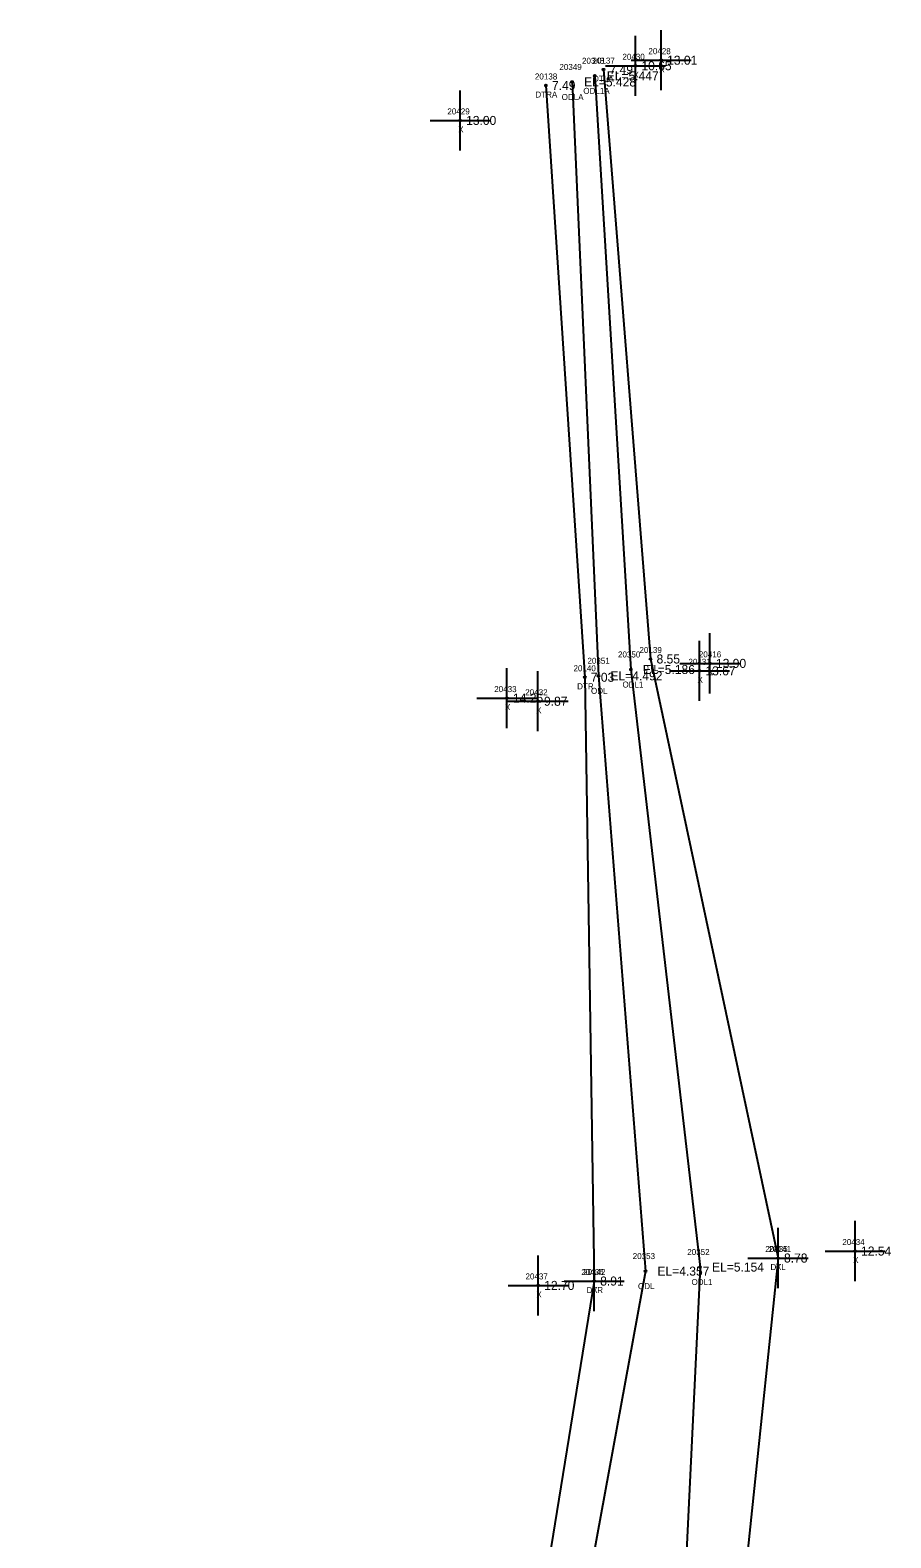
# Model space of a CAD drawing. Extents: x 2072302 to 2072980, y 127650 to 129736.
# Drawn here: x 2072308.2 to 2072451.4, y 128316.1 to 128566.9 of the extents above; entities that cross this region are included whole.
import ezdxf

# ---------------------------------------------------------------- set-up
doc = ezdxf.new("R2010")
doc.units = 0
for name, color, linetype in [('RD_EX_H2O', 7, 'Continuous'), ('RD_EX_H2O_txCode', 7, 'Continuous'), ('RD_EX_Misc', 7, 'Continuous'), ('RD_EX_Misc_txCode', 7, 'Continuous'), ('RD_EX_TX_H2O_ELEV', 7, 'Continuous'), ('RD_EX_TX_Misc_ELEV', 7, 'Continuous'), ('RD_SMD_Locator', 7, 'Continuous')]:
    doc.layers.add(name, color=color, linetype=linetype)

msp = doc.modelspace()

# ---------------------------------------------------------------- linework, layer by layer
at = {"layer": 'RD_EX_H2O'}
for points in [[(2072402.16, 128559.26), (2072408.19, 128460.51), (2072419.68, 128361.12), (2072413.76, 128237.7), (2072402.36, 128177.9), (2072384.5, 128133.27), (2072364.13, 128111.41), (2072366.88, 128103.31), (2072335.48, 128099.87), (2072319.81, 128071.7)], [(2072403.62, 128560.29), (2072411.45, 128462.26), (2072432.66, 128362.62), (2072419.56, 128236.49), (2072406.7, 128177.6), (2072390.06, 128127.17), (2072380.51, 128114.72)], [(2072394.05, 128557.65), (2072400.51, 128459.22), (2072402.07, 128358.79), (2072383.51, 128244.18), (2072363.41, 128182.49), (2072364.78, 128146.69), (2072330.57, 128113.46), (2072324.79, 128105.03), (2072308.22, 128075.71)], [(2072398.39, 128558.24), (2072402.78, 128459.46), (2072410.6, 128360.44), (2072388.96, 128242.4), (2072374.63, 128179.98), (2072371.63, 128143.83), (2072337.87, 128113.26), (2072328.43, 128104.04), (2072312.51, 128073.95)]]:
    msp.add_lwpolyline(points, dxfattribs=at)
at = {"layer": 'RD_EX_Misc'}
for p, q in [((2072413.21, 128556.86), (2072413.21, 128566.86)), ((2072408.93, 128555.93), (2072408.93, 128565.93)), ((2072408.21, 128561.86), (2072418.21, 128561.86)), ((2072403.93, 128560.93), (2072413.93, 128560.93)), ((2072379.76, 128546.84), (2072379.76, 128556.84)), ((2072374.76, 128551.84), (2072384.76, 128551.84)), ((2072421.34, 128456.53), (2072421.34, 128466.53)), ((2072419.58, 128455.29), (2072419.58, 128465.29)), ((2072387.56, 128450.75), (2072387.56, 128460.75)), ((2072416.34, 128461.53), (2072426.34, 128461.53)), ((2072392.72, 128450.23), (2072392.72, 128460.23)), ((2072414.58, 128460.29), (2072424.58, 128460.29)), ((2072382.56, 128455.75), (2072392.56, 128455.75)), ((2072387.72, 128455.23), (2072397.72, 128455.23)), ((2072445.48, 128358.78), (2072445.48, 128368.78)), ((2072432.66, 128357.62), (2072432.66, 128367.62)), ((2072392.76, 128353.06), (2072392.76, 128363.06)), ((2072402.07, 128353.79), (2072402.07, 128363.79)), ((2072440.48, 128363.78), (2072450.48, 128363.78)), ((2072427.66, 128362.62), (2072437.66, 128362.62)), ((2072387.76, 128358.06), (2072397.76, 128358.06)), ((2072397.07, 128358.79), (2072407.07, 128358.79))]:
    msp.add_line(p, q, dxfattribs=at)
at = {"layer": 'RD_SMD_Locator'}
for centre in [(2072408.93, 128560.93), (2072413.21, 128561.86), (2072402.16, 128559.26), (2072403.62, 128560.29), (2072394.05, 128557.65), (2072398.39, 128558.24), (2072379.76, 128551.84), (2072411.45, 128462.26), (2072421.34, 128461.53), (2072400.51, 128459.22), (2072402.78, 128459.46), (2072408.19, 128460.51), (2072419.58, 128460.29), (2072387.56, 128455.75), (2072392.72, 128455.23), (2072445.48, 128363.78), (2072410.6, 128360.44), (2072419.68, 128361.12), (2072432.66, 128362.62), (2072432.66, 128362.62), (2072392.76, 128358.06), (2072402.07, 128358.79), (2072402.07, 128358.79)]:
    msp.add_circle(centre, 0.15, dxfattribs=at)

# ---------------------------------------------------------------- texts
at = {"layer": 'RD_EX_H2O_txCode'}
for s, p in [('20349', (2072396.28, 128560.24)), ('20348', (2072400.04, 128561.26)), ('20137', (2072401.79, 128561.29)), ('20138', (2072392.21, 128558.65)), ('DTLA', (2072401.89, 128558.29)), ('DTRA', (2072392.29, 128555.65)), ('ODLA', (2072396.66, 128555.24)), ('ODL1A', (2072400.26, 128556.26)), ('20350', (2072406.03, 128462.51)), ('20139', (2072409.61, 128463.26)), ('20140', (2072398.63, 128460.22)), ('20351', (2072400.95, 128461.46)), ('DTL', (2072410.21, 128460.26)), ('ODL1', (2072406.78, 128457.51)), ('DTR', (2072399.24, 128457.22)), ('ODL', (2072401.54, 128456.46)), ('20353', (2072408.48, 128362.44)), ('20352', (2072417.56, 128363.12)), ('20141', (2072431.11, 128363.62)), ('20142', (2072400.23, 128359.79)), ('DTL', (2072431.41, 128360.62)), ('ODL', (2072409.36, 128357.44)), ('ODL1', (2072418.27, 128358.12)), ('DTR', (2072400.8, 128356.79))]:
    msp.add_text(s, height=1, dxfattribs=at).set_placement(p)
at = {"layer": 'RD_EX_Misc_txCode'}
for s, p in [('20428', (2072411.09, 128562.86)), ('20430', (2072406.77, 128561.93)), ('X', (2072408.61, 128558.93)), ('X', (2072412.89, 128559.86)), ('20429', (2072377.64, 128552.84)), ('X', (2072379.44, 128549.84)), ('20416', (2072419.49, 128462.53)), ('20431', (2072417.75, 128461.29)), ('X', (2072419.27, 128458.29)), ('X', (2072421.03, 128459.53)), ('20433', (2072385.44, 128456.75)), ('20432', (2072390.6, 128456.23)), ('X', (2072387.24, 128453.75)), ('X', (2072392.4, 128453.23)), ('20434', (2072443.36, 128364.78)), ('20435', (2072430.54, 128363.62)), ('20436', (2072399.93, 128359.79)), ('X', (2072432.34, 128360.62)), ('X', (2072445.16, 128361.78)), ('20437', (2072390.64, 128359.06)), ('X', (2072392.45, 128356.06)), ('X', (2072401.75, 128356.79))]:
    msp.add_text(s, height=1, dxfattribs=at).set_placement(p)
at = {"layer": 'RD_EX_TX_H2O_ELEV'}
for s, p in [('7.49', (2072404.62, 128559.54)), ('EL=5.428', (2072400.39, 128557.49)), ('EL=5.447', (2072404.16, 128558.51)), ('7.49', (2072395.05, 128556.9)), ('EL=5.186', (2072410.19, 128459.76)), ('8.55', (2072412.45, 128461.51)), ('7.03', (2072401.51, 128458.47)), ('EL=4.492', (2072404.78, 128458.71)), ('8.78', (2072433.66, 128361.87)), ('EL=4.357', (2072412.6, 128359.69)), ('EL=5.154', (2072421.68, 128360.37)), ('8.91', (2072403.07, 128358.04))]:
    msp.add_text(s, height=1.5, dxfattribs=at).set_placement(p)
at = {"layer": 'RD_EX_TX_Misc_ELEV'}
for s, p in [('10.65', (2072409.93, 128560.18)), ('13.01', (2072414.21, 128561.11)), ('13.00', (2072380.76, 128551.09)), ('13.67', (2072420.58, 128459.54)), ('13.90', (2072422.34, 128460.78)), ('14.26', (2072388.56, 128455)), ('9.87', (2072393.72, 128454.48)), ('8.78', (2072433.66, 128361.87)), ('12.54', (2072446.48, 128363.03)), ('12.70', (2072393.76, 128357.31)), ('8.91', (2072403.07, 128358.04))]:
    msp.add_text(s, height=1.5, dxfattribs=at).set_placement(p)

doc.saveas('drawing.dxf')
